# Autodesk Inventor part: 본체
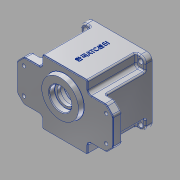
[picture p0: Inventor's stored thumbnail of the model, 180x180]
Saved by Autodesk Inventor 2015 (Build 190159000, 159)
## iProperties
Created: 2016-02
Part Number: 본체
Material: Aluminum 6061
Document SubType Name: Modeling
Designer: Administrator
Density: 2.7 g/cm^3
Appearance: Aluminum - Flat
Mass: 873.708 g
Surface Area: 761.421 cm^2
Volume: 323.596 cm^3
Author: Administrator
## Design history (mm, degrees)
sketch "Sketch1"
  geometry: L1 (-70, -30)-(70, -30); L2 (70, -30)-(70, 30); L3 (70, 30)-(-70, 30); L4 (-70, 30)-(-70, -30); L5 (-70, -30)-(70, 30); L6 (70, -30)-(-70, 30); 1 further point
  constraints: 12 end point, 2 midpoint, 2 parallel, 1 horizontal, 1 perpendicular
  dimensions: "d0" = 140 distance of L2.end L3.end; "d1" = 60 distance of L3.end L1.start
extrude "Extrusion1" new body sketch "Sketch1" distance "d2" = 13; taper "d3" = 0 deg
sketch "Sketch2"
  geometry: L1 (33, -47)-(-33, -47); L2 (-33, -47)-(-33, 47); L3 (-33, 47)-(33, 47); L4 (33, 47)-(33, -47); L5 (33, -47)-(-33, 47); L6 (-33, -47)-(33, 47); 1 further point
  constraints: 12 end point, 2 midpoint, 2 parallel, 1 horizontal, 1 perpendicular
  dimensions: "d4" = 66 distance of L2.end L3.end; "d5" = 94 distance of L3.end L1.start
extrude "Extrusion2" join sketch "Sketch2" distance "d6" = 80; taper "d7" = 0 deg
chamfer "Chamfer1" distance "d8" = 10; stored, may be unused: second distance "d9" = 2, angle "d10" = 45 deg
sketch "Sketch4"
  geometry: L1 (47, -47)-(-47, -47); L2 (-47, -47)-(-47, 47); L3 (-47, 47)-(47, 47); L4 (47, 47)-(47, -47); L5 (47, -47)-(-47, 47); L6 (-47, -47)-(47, 47); 1 further point
  constraints: 12 end point, 2 midpoint, 2 parallel, 1 horizontal, 1 perpendicular
  dimensions: "d11" = 94 distance of L1.end L2.end; "d12" = 94 distance of L2.end L3.end
extrude "Extrusion3" join sketch "Sketch4" distance "d13" = 10; taper "d14" = 0 deg
fillet "Fillet1" dims "d15" = 8
sketch "Sketch5"
  geometry: L1 (47, -30)-(-47, -30); L2 (-47, -30)-(-47, 30); L3 (-47, 30)-(47, 30); L4 (47, 30)-(47, -30); L5 (47, -30)-(-47, 30); L6 (-47, -30)-(47, 30); 1 further point
  constraints: 12 end point, 2 midpoint, 2 parallel, 1 horizontal, 1 perpendicular
  dimensions: "d16" = 60 distance of L3.end L1.start; "d17" = 94 distance of L2.end L3.end
extrude "Extrusion4" join sketch "Sketch5" stored distance "d18" = 62; taper "d19" = 0 deg
sketch "Sketch6"
  geometry: C1 r 43 at (0, 0); 1 further point
  constraints: 1 centre point, 1 coincident
  dimensions: "d20" = 86 diameter of C1
extrude "Extrusion5" cut sketch "Sketch6" distance "d21" = 9; taper "d22" = 0 deg
sketch "Sketch7"
  geometry: C1 r 40 at (0, 0); 1 further point
  constraints: 1 centre point, 1 coincident
  dimensions: "d23" = 80 diameter of C1
extrude "Extrusion6" cut sketch "Sketch7" distance "d24" = 62; taper "d25" = 0 deg
sketch "Sketch8"
  geometry: A1 r 21 centre (0, -11) between (-8.978, 7.984) and (8.978, 7.984); A2 r 15 centre (0, 20) between (8.978, 7.984) and (-8.978, 7.984); 1 further point
  constraints: 4 point on circle, 2 centre point, 2 vertical alignment
  dimensions: "d26" = 42 diameter of A1; "d27" = 11 distance of point (0, 0) A1.centre; "d28" = 30 diameter of A2; "d29" = 20 distance of point (0, 0) A2.centre
extrude "Extrusion7" join sketch "Sketch8" distance "d30" = 7; taper "d31" = 0 deg
fillet "Fillet2" dims "d32" = 3
sketch "Sketch9"
  geometry: C1 r 28 at (0, 11); 1 further point
  constraints: 1 centre point, 1 vertical alignment
  dimensions: "d33" = 56 diameter of C1; "d34" = 11 distance of point (0, 0) C1.centre
extrude "Extrusion8" join sketch "Sketch9" distance "d35" = 7; taper "d36" = -10 deg
sketch "Sketch10"
  geometry: C1 r 17.5 at (0, -11); A1 r 21 centre (0, -11) between (-12.163, 6.119) and (12.163, 6.119) reference; 1 further point
  constraints: 1 centre point, 1 concentric
  dimensions: "d37" = 35 diameter of C1
extrude "Extrusion9" cut sketch "Sketch10" distance "d38" = 10; taper "d39" = 0 deg
sketch "Sketch11"
  geometry: C1 r 12.5 at (0, 0); C2 r 17.5 at (0, 0) reference; 1 further point
  constraints: 1 centre point, 1 concentric
  dimensions: "d40" = 25 diameter of C1
extrude "Extrusion10" cut sketch "Sketch11" distance "d41" = 5; taper "d42" = 0 deg
sketch "Sketch12"
  geometry: C1 r 16 at (0, 0); C2 r 12.5 at (0, 0) reference; 1 further point
  constraints: 1 centre point, 1 concentric
  dimensions: "d43" = 32 diameter of C1
extrude "Extrusion11" cut sketch "Sketch12" distance "d44" = 8; taper "d45" = 0 deg
sketch "Sketch13"
  geometry: C1 r 11 at (0, 20); A1 r 15 centre (0, 20) between (11.584, 10.47) and (-11.584, 10.47) reference; 1 further point
  constraints: 1 centre point, 1 concentric
  dimensions: "d46" = 22 diameter of C1
extrude "Extrusion12" cut sketch "Sketch13" distance "d47" = 7; taper "d48" = 0 deg
sketch "Sketch14"
  geometry: C1 r 9.5 at (0, 0); C2 r 11 at (0, 0) reference; 1 further point
  constraints: 1 centre point, 1 concentric
  dimensions: "d49" = 19 diameter of C1
extrude "Extrusion13" cut sketch "Sketch14" distance "d50" = 1; taper "d51" = 0 deg
chamfer "Chamfer2" distance "d52" = 1; stored, may be unused: second distance "d53" = 2, angle "d54" = 45 deg
fillet "Fillet3" dims "d55" = 2
sketch "Sketch17"
  geometry: C1 r 4.5 at (60, 19); C2 r 4.5 at (60, -19); C3 r 4.5 at (-60, -19); C4 r 4.5 at (-60, 19); C5 r 12.5 at (0, -11) reference; 1 further point
  constraints: 4 centre point, 2 horizontal alignment, 2 vertical alignment
  dimensions: "d72" = 9 diameter of C2; "d73" = 9 diameter of C1; "d74" = 9 diameter of C4; "d75" = 9 diameter of C3; "d76" = 38 distance of C2.centre C1.centre; "d77" = 19 vertical distance of point (0, 0) C1.centre; "d78" = 120 distance of C1.centre C4.centre; "d79" = 60 horizontal distance of C5.centre C4.centre
extrude "Extrusion16" cut sketch "Sketch17" distance "d80" = 4; taper "d81" = 0 deg
sketch "Sketch18"
  geometry: C1 r 4.5 at (0, 0) reference; C2 r 4.5 at (0, -38) reference; C3 r 4.5 at (-120, -38) reference; C4 r 4.5 at (-120, 0) reference; C5 r 2.5 at (0, 0); C6 r 2.5 at (0, -38); C7 r 2.5 at (-120, 0); C8 r 2.5 at (-120, -38); 1 further point
  constraints: 4 centre point, 4 coincident
  dimensions: "d82" = 5 diameter of C8; "d83" = 5 diameter of C7; "d84" = 5 diameter of C6; "d85" = 5 diameter of C5
extrude "Extrusion17" cut sketch "Sketch18" stored distance "d86" = 4; taper "d87" = 0 deg
sketch "Sketch19"
  geometry: C1 r 3.5 at (-40, 40); C2 r 3.5 at (40, 40); C3 r 3.5 at (40, -40); C4 r 3.5 at (-40, -40); 1 further point
  constraints: 4 centre point, 2 horizontal alignment, 2 vertical alignment
  dimensions: "d134" = 7 diameter of C1; "d135" = 7 diameter of C2; "d136" = 7 diameter of C3; "d137" = 7 diameter of C4; "d138" = 80 distance of C1.centre C2.centre; "d139" = 80 distance of C3.centre C2.centre; "d140" = 40 horizontal distance of C1.centre point (0, 0); "d141" = 40 horizontal distance of point (0, 0) C1.centre
extrude "Extrusion18" cut sketch "Sketch19" stored distance "d92" = 4; taper "d93" = 0 deg
sketch "Sketch20"
  geometry: A1 r 36 centre (0, 0) between (36, 0) and (-36, 0); A2 r 4 centre (36, 0) between (35.852, 3.997) and (35.852, -3.997); A3 r 4 centre (-36, 0) between (-35.852, -3.997) and (-35.852, 3.997); A4 r 3.5 centre (-35.722, -7.495) between (-35.778, -3.995) and (-39.148, -8.214); A5 r 40 centre (0, 0) between (-39.148, -8.214) and (39.148, -8.214) reference; A6 r 3.5 centre (-35.722, 7.495) between (-39.148, 8.214) and (-35.778, 3.995); A7 r 3.5 centre (35.722, -7.495) between (39.148, -8.214) and (35.778, -3.995); A8 r 3.5 centre (35.722, 7.495) between (35.778, 3.995) and (39.148, 8.214); 1 further point
  constraints: 26 point on circle, 8 tangent, 7 centre point, 2 horizontal alignment, 1 coincident
  dimensions: "d94" = 36 radius of A1; "d95" = 4 radius of A2; "d96" = 4 radius of A3; "d97" = 3.5 radius of A4; "d98" = 3.5 radius of A6; "d99" = 3.5 radius of A7; "d100" = 3.5 radius of A8
extrude "Extrusion19" join sketch "Sketch20" stored distance "d101" = 4; taper "d102" = 0 deg
sketch "Sketch21"
  geometry: A1 r 4 centre (36, 0) between (35.852, 3.997) and (35.852, -3.997) reference; A2 r 4 centre (-36, 0) between (-35.852, -3.997) and (-35.852, 3.997) reference; A3 r 4 centre (-36, 0) between (-35.852, -3.997) and (-35.852, 3.997) reference; 3 further points
  constraints: 2 coincident
hole "Hole1" sketch "Sketch21" at (36, 0), (-36, 0) diameter "d103" = 3.242; stored, may be unused: countersink angle "d107" = 90 deg, drill point angle "d109" = 118 deg; dims "d104" = 7, "d105" = 4, "d106" = 2, "d108" = 9
fillet "Fillet4" dims "d113" = 0.3
fillet "Fillet5" dims "d114" = 5
fillet "Fillet6" dims "d118" = 5
fillet "Fillet7" dims "d119" = 2
fillet "Fillet8" dims "d120" = 2
fillet "Fillet9" dims "d121" = 2
fillet "Fillet10" dims "d122" = 2
chamfer "Chamfer3" distance "d123" = 1; stored, may be unused: second distance "d124" = 2, angle "d125" = 45 deg
fillet "Fillet11" dims "d126" = 2
fillet "Fillet12" dims "d127" = 2
sketch "Sketch24"
  geometry: L1 (-31, 47)-(31, 47) reference; L2 (-33, 35)-(-33, 45) reference; L3 (-57.929, 30)-(-38, 30) reference; L4 (-68.536, 21.464)-(-61.464, 28.536) reference; L5 (-70, -17.929)-(-70, 17.929) reference; L6 (-61.464, -28.536)-(-68.536, -21.464) reference; L7 (-38, -30)-(-57.929, -30) reference; L8 (-33, -45)-(-33, -35) reference; L9 (31, -47)-(-31, -47) reference; L10 (33, -35)-(33, -45) reference; L11 (57.929, -30)-(38, -30) reference; L12 (68.536, -21.464)-(61.464, -28.536) reference; L13 (70, 17.929)-(70, -17.929) reference; L14 (61.464, 28.536)-(68.536, 21.464) reference; L15 (38, 30)-(57.929, 30) reference; L16 (33, 45)-(33, 35) reference; L17 (-32, -45)-(-32, -35); L18 (-38, -29)-(-57.929, -29); L19 (-60.757, -27.828)-(-67.828, -20.757); L20 (-69, -17.929)-(-69, 17.929); L21 (-67.828, 20.757)-(-60.757, 27.828); L22 (-57.929, 29)-(-38, 29); L23 (-32, 35)-(-32, 45); L24 (-31, 46)-(31, 46); L25 (32, 45)-(32, 35); L26 (38, 29)-(57.929, 29); L27 (60.757, 27.828)-(67.828, 20.757); L28 (69, 17.929)-(69, -17.929); L29 (67.828, -20.757)-(60.757, -27.828); L30 (57.929, -29)-(38, -29); L31 (32, -35)-(32, -45); L32 (31, -46)-(-31, -46); C1 r 2.5 at (-60, 19) reference; C2 r 2.5 at (60, -19) reference; C3 r 2.5 at (60, 19) reference; C4 r 2.5 at (-60, -19) reference; C5 r 28 at (0, 11) reference; A1 r 2 centre (31, 45) between (33, 45) and (31, 47) reference; A2 r 2 centre (-31, 45) between (-31, 47) and (-33, 45) reference; A3 r 5 centre (-38, 35) between (-38, 30) and (-33, 35) reference; A4 r 5 centre (-57.929, 25) between (-57.929, 30) and (-61.464, 28.536) reference; A5 r 5 centre (-65, 17.929) between (-68.536, 21.464) and (-70, 17.929) reference; A6 r 5 centre (-65, -17.929) between (-70, -17.929) and (-68.536, -21.464) reference; A7 r 5 centre (-57.929, -25) between (-61.464, -28.536) and (-57.929, -30) reference; A8 r 5 centre (-38, -35) between (-33, -35) and (-38, -30) reference; A9 r 2 centre (-31, -45) between (-33, -45) and (-31, -47) reference; A10 r 2 centre (31, -45) between (31, -47) and (33, -45) reference; A11 r 5 centre (38, -35) between (38, -30) and (33, -35) reference; A12 r 5 centre (57.929, -25) between (57.929, -30) and (61.464, -28.536) reference; A13 r 5 centre (65, -17.929) between (68.536, -21.464) and (70, -17.929) reference; A14 r 5 centre (65, 17.929) between (70, 17.929) and (68.536, 21.464) reference; A15 r 5 centre (57.929, 25) between (61.464, 28.536) and (57.929, 30) reference; A16 r 5 centre (38, 35) between (33, 35) and (38, 30) reference; A17 r 1 centre (-31, -45) between (-32, -45) and (-31, -46); A18 r 6 centre (-38, -35) between (-32, -35) and (-38, -29); A19 r 4 centre (-57.929, -25) between (-60.757, -27.828) and (-57.929, -29); A20 r 4 centre (-65, -17.929) between (-69, -17.929) and (-67.828, -20.757); A21 r 4 centre (-65, 17.929) between (-67.828, 20.757) and (-69, 17.929); A22 r 4 centre (-57.929, 25) between (-57.929, 29) and (-60.757, 27.828); A23 r 6 centre (-38, 35) between (-38, 29) and (-32, 35); A24 r 1 centre (-31, 45) between (-31, 46) and (-32, 45); A25 r 1 centre (31, 45) between (32, 45) and (31, 46); A26 r 6 centre (38, 35) between (32, 35) and (38, 29); A27 r 4 centre (57.929, 25) between (60.757, 27.828) and (57.929, 29); A28 r 4 centre (65, 17.929) between (69, 17.929) and (67.828, 20.757); A29 r 4 centre (65, -17.929) between (67.828, -20.757) and (69, -17.929); A30 r 4 centre (57.929, -25) between (57.929, -29) and (60.757, -27.828); A31 r 6 centre (38, -35) between (38, -29) and (32, -35); A32 r 1 centre (31, -45) between (31, -46) and (32, -45); 1 further point
  constraints: 32 end point, 32 point on circle, 16 centre point, 31 other
  dimensions: "d128" = 1 distance between parallel lines of L9 L32
extrude "Extrusion22" cut sketch "Sketch24" distance "d129" = 1; taper "d130" = 0 deg
sketch "Sketch25"
  geometry: L1 (78, 0)-(0, 0) reference; 2 further points
  constraints: 1 vertical alignment, 1 other
  dimensions: "d131" = 40 distance from line of L1 point (39, -40)
emboss "Emboss1" sketch "Sketch25" dims "d132" = 0.5, "d133" = 0
fillet "Fillet13" dims "d142" = 0.3
body "Solid1"
node "Projected Loop3"
